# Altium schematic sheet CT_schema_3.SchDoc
size 298 x 230 mm
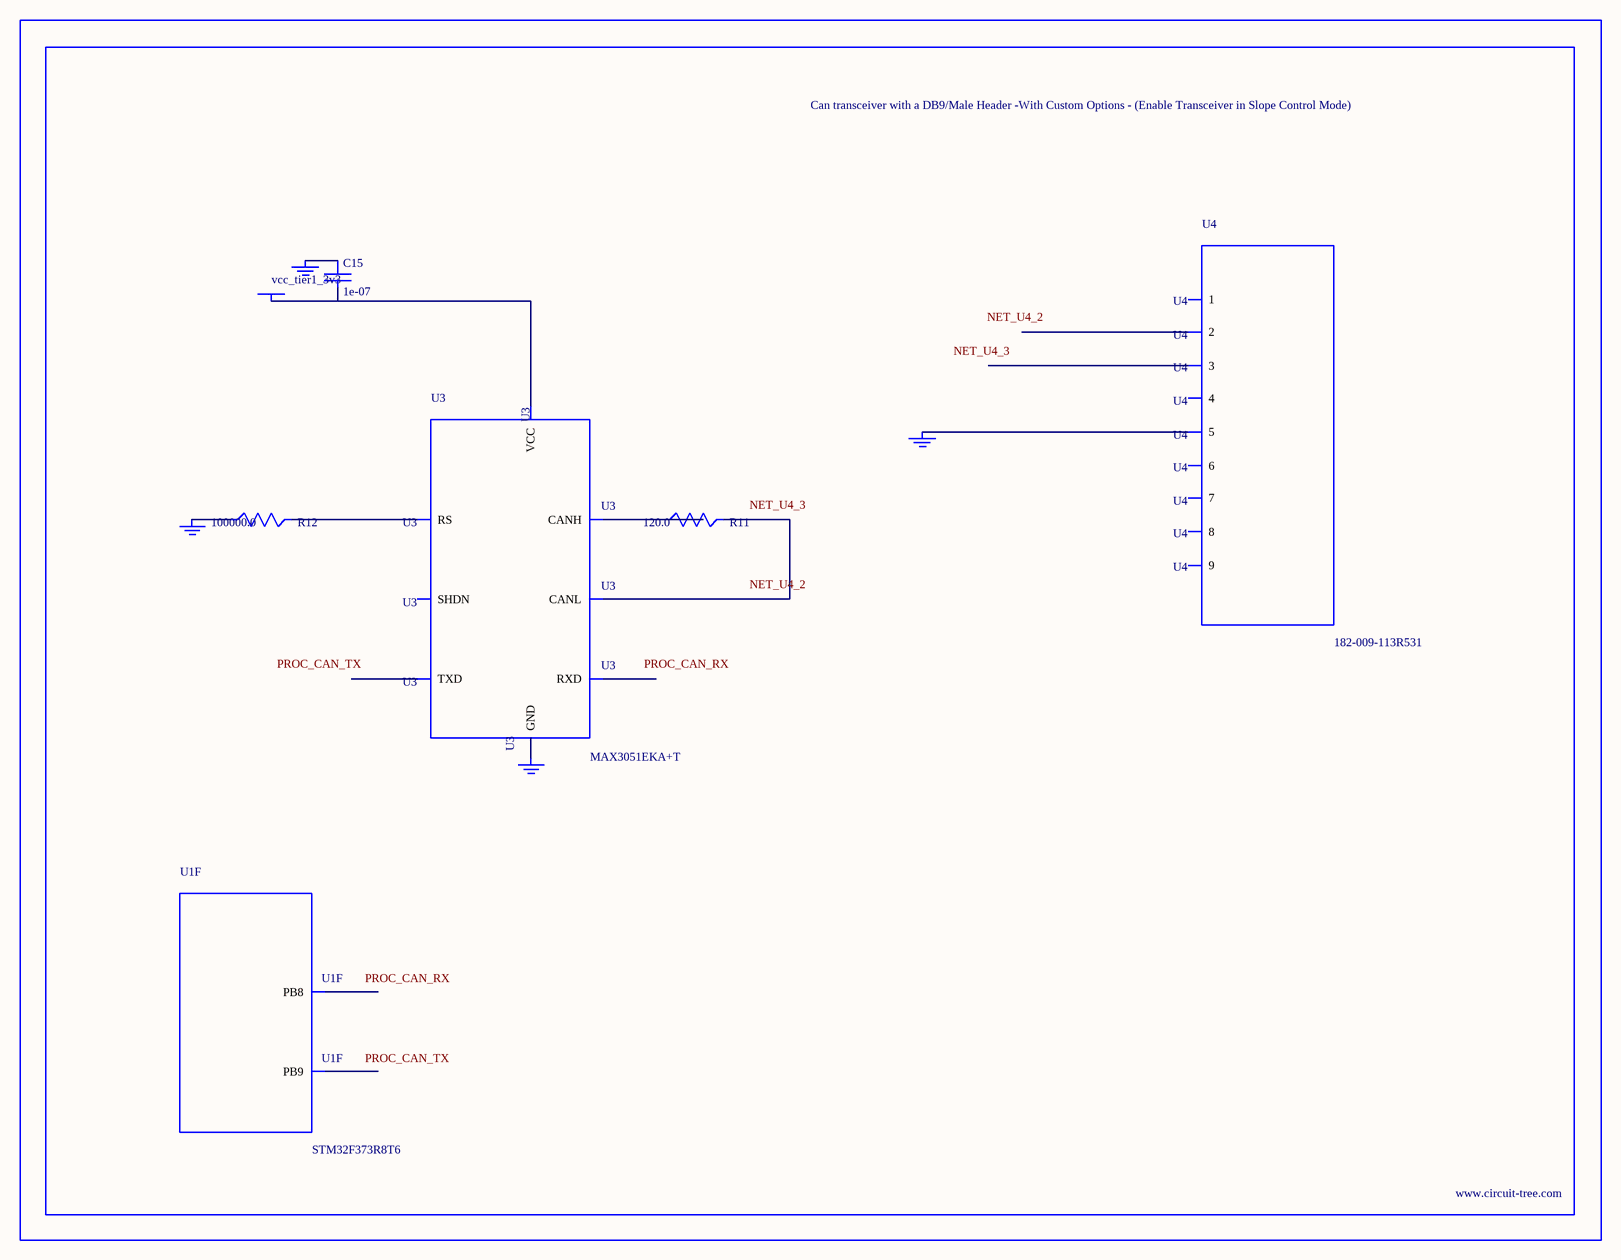
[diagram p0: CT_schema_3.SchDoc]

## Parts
BORDER2  (no value)
C15  1e-07  [C0402]
GND_INSTANCE_2_0  (no value)
GND_INSTANCE_2_1  (no value)
GND_INSTANCE_2_2  (no value)
GND_INSTANCE_2_3  (no value)
POWER_INSTANCE_2_0  vcc_tier1_3v3
R11  120.0  [R0603]
R12  100000.0  [R0603]
U1  STM32F373R8T6  [LQFP64]  (part F of 7)
U3  MAX3051EKA+T  [SOT-23-8]
U4  182-009-113R531  [182-009-MALE]

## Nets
NetC15_1: C15.1 GND_INSTANCE_2_0.0(GND)
NetC15_2: C15.2 POWER_INSTANCE_2_0.0(PWR) U3.3(VCC)
NetGND_INSTANCE_2_1_0: GND_INSTANCE_2_1.0(GND) R12.1
NetGND_INSTANCE_2_2_0: GND_INSTANCE_2_2.0(GND) U3.2(GND)
NetGND_INSTANCE_2_3_0: GND_INSTANCE_2_3.0(GND) U4.5
NetR11_1: R11.1 U3.7(CANH)
NetR11_2: R11.2 U3.6(CANL)
NetR12_2: R12.2 U3.8(RS)

Not connected (* = marked no-connect by the designer): U1 61(PB8) 62(PB9); U3 1(TXD) 4(RXD) 5(SHDN); U4 1 2 3 4 6 7 8 9

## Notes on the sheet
- Labels drawn without touching a wire or pin: NET_U4_2, NET_U4_3, PROC_CAN_RX, PROC_CAN_TX

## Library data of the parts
BORDER2 = BORDER_PAGE2
C15 = C0402C104K3RACTU
GND_INSTANCE_2_0-GND_INSTANCE_2_3 = GND
POWER_INSTANCE_2_0 = PWR
R11 = RC0603JR-07120RL
R12 = RC0603JR-07100KL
